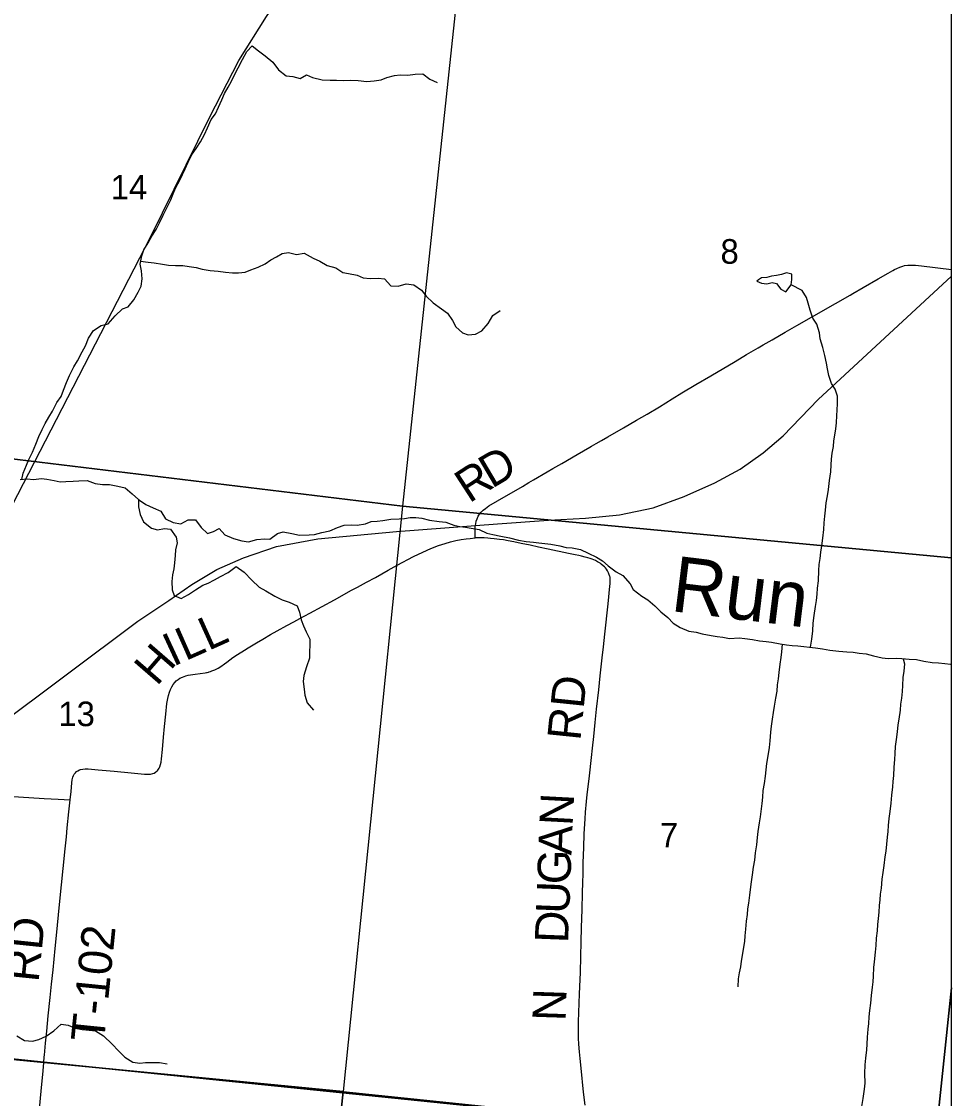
# Model space of a CAD drawing. Extents: x 0 to 1067, y 0 to 440.
# Drawn here: x 803.255 to 804.84, y 353.302 to 355.137 of the extents above; entities that cross this region are included whole.
import ezdxf

# ---------------------------------------------------------------- set-up
doc = ezdxf.new("R2010")
doc.units = 0
for name, color, linetype in [('GM_X_Minor_Lake', 7, 'Continuous'), ('GM_X_Minor_River', 7, 'Continuous'), ('GM_X_Minor_River_Text', 7, 'Continuous'), ('GM_X_Rail_Line', 7, 'Continuous'), ('GM_X_Section', 7, 'Continuous'), ('GM_X_Section_Text', 7, 'Continuous'), ('GM_X_Township_Road', 7, 'Continuous'), ('GM_X_Township_Road_Text', 7, 'Continuous'), ('GM_X_US_Shield', 7, 'Continuous')]:
    doc.layers.add(name, color=color, linetype=linetype)

msp = doc.modelspace()

# ---------------------------------------------------------------- linework, layer by layer
at = {"layer": 'GM_X_Minor_Lake'}
for points in [[(804.5669, 354.6882), (804.5678, 354.6973), (804.5679, 354.7061), (804.5589, 354.7085), (804.5505, 354.7059), (804.5417, 354.7038), (804.5333, 354.7028), (804.5253, 354.7006), (804.5162, 354.7), (804.5113, 354.6964)], [(804.5113, 354.6964), (804.5085, 354.6944), (804.5161, 354.6908), (804.5256, 354.6896), (804.5343, 354.6921), (804.5419, 354.6905), (804.5493, 354.6809), (804.5576, 354.6762), (804.5669, 354.6882)]]:
    msp.add_lwpolyline(points, dxfattribs=at)
at = {"layer": 'GM_X_Minor_River'}
for points in [[(803.2553, 354.3567), (803.2575, 354.3674), (803.2637, 354.3806), (803.2673, 354.3908), (803.2739, 354.4029), (803.2794, 354.4169), (803.2845, 354.4297), (803.2904, 354.4414), (803.2951, 354.4516), (803.3017, 354.4626), (803.3079, 354.4727), (803.3154, 354.4874), (803.3223, 354.4976), (803.3267, 354.5086), (803.3314, 354.5218), (803.3365, 354.5339), (803.3443, 354.5486), (803.3502, 354.5588), (803.3584, 354.5742), (803.3638, 354.5844), (803.3693, 354.5972), (803.3775, 354.6104), (803.3905, 354.619), (803.4027, 354.6219), (803.4147, 354.6354), (803.427, 354.6474), (803.4365, 354.6506), (803.4466, 354.6627), (803.454, 354.6759), (803.4587, 354.6857), (803.4604, 354.6986), (803.4594, 354.7119), (803.4569, 354.7233), (803.4598, 354.7377), (803.4637, 354.7475), (803.4711, 354.7596), (803.477, 354.7709), (803.4843, 354.7822), (803.4902, 354.7939), (803.4965, 354.8067), (803.5023, 354.8184), (803.5094, 354.8327), (803.5137, 354.8429), (803.5176, 354.8527), (803.5246, 354.8663), (803.5293, 354.8761), (803.534, 354.8859), (803.5391, 354.8969), (803.5461, 354.9105), (803.5524, 354.9206), (803.5601, 354.9319), (803.5667, 354.944), (803.5722, 354.9557), (803.5781, 354.9697), (803.5855, 354.9794), (803.5906, 354.9908), (803.5964, 355.0032), (803.6012, 355.0142), (803.6074, 355.0247), (803.6128, 355.0353), (803.6183, 355.047), (803.6242, 355.0579), (803.6316, 355.0719), (803.639, 355.0854), (803.6479, 355.0956), (803.6591, 355.0867), (803.6704, 355.0782), (803.6832, 355.0674), (803.6929, 355.0547), (803.706, 355.0443), (803.7177, 355.0433), (803.7298, 355.0394), (803.7409, 355.0461), (803.7511, 355.0414), (803.7674, 355.0373), (803.7811, 355.0368), (803.7921, 355.037), (803.8046, 355.0364), (803.8156, 355.0367), (803.8289, 355.0361), (803.8437, 355.0348), (803.8562, 355.0357), (803.868, 355.0375), (803.8776, 355.0415), (803.8909, 355.0447), (803.9004, 355.0461), (803.9137, 355.0456), (803.9262, 355.0473), (803.9392, 355.0475), (803.9512, 355.0386), (803.9632, 355.0327)], [(803.458, 354.7285), (803.4706, 354.7265), (803.4809, 354.7256), (803.4953, 354.7232), (803.5055, 354.7219), (803.5173, 354.7213), (803.5298, 354.7212), (803.5408, 354.7195), (803.5525, 354.7174), (803.5627, 354.715), (803.5764, 354.7125), (803.59, 354.7116), (803.6025, 354.7099), (803.6143, 354.7086), (803.6249, 354.7088), (803.6363, 354.7098), (803.6458, 354.7135), (803.6581, 354.7183), (803.6703, 354.7238), (803.6799, 354.7305), (803.6898, 354.7357), (803.6994, 354.7413), (803.7101, 354.7434), (803.7237, 354.7398), (803.737, 354.7419), (803.7521, 354.7333), (803.7634, 354.7282), (803.7758, 354.7208), (803.7906, 354.7172), (803.8026, 354.7091), (803.8124, 354.7074), (803.8272, 354.7046), (803.8374, 354.6999), (803.8495, 354.6989), (803.8628, 354.6995), (803.8734, 354.6986), (803.8843, 354.6867), (803.8972, 354.6861), (803.9105, 354.6901), (803.9238, 354.6884), (803.9369, 354.6791), (803.9448, 354.6691), (803.9564, 354.6572), (803.9707, 354.6471), (803.9808, 354.6398), (803.9897, 354.6271), (803.9953, 354.6164), (804.0065, 354.6064), (804.0163, 354.6028), (804.0289, 354.6038), (804.0396, 354.6097), (804.0504, 354.6221), (804.0582, 354.636), (804.0708, 354.6442)], [(804.5997, 354.0708), (804.602, 354.0846), (804.6037, 354.0986), (804.6046, 354.1119), (804.6063, 354.1248), (804.6081, 354.1403), (804.6101, 354.1502), (804.6114, 354.1612), (804.6119, 354.1714), (804.6133, 354.1839), (804.6143, 354.2014), (804.6148, 354.2117), (804.6161, 354.2219), (804.6177, 354.2325), (804.619, 354.2435), (804.6207, 354.2564), (804.6225, 354.2712), (804.6234, 354.2829), (804.6243, 354.2939), (804.6252, 354.3042), (804.6265, 354.3167), (804.6286, 354.3288), (804.6307, 354.3394), (804.6324, 354.3546), (804.6345, 354.3694), (804.635, 354.3812), (804.6356, 354.391), (804.6369, 354.4013), (804.6389, 354.4126), (804.6398, 354.4221), (804.6411, 354.432), (804.6428, 354.4429), (804.6441, 354.4532), (804.645, 354.4653), (804.6451, 354.4748), (804.6457, 354.4858), (804.6458, 354.4984), (804.6418, 354.5106), (804.6355, 354.5202), (804.6308, 354.5339), (804.6287, 354.5449), (804.6273, 354.5544), (804.624, 354.5678), (804.6208, 354.5815), (804.6165, 354.5964), (804.6151, 354.6063), (804.6104, 354.6212), (804.6037, 354.6311), (804.5993, 354.6449), (804.5961, 354.6571), (804.5928, 354.6666), (804.5858, 354.6785), (804.5669, 354.6882)], [(803.2524, 354.3565), (803.2645, 354.3575), (803.2751, 354.3562), (803.2888, 354.3579), (803.2983, 354.357), (803.3108, 354.3546), (803.321, 354.3525), (803.3305, 354.3528)], [(803.3305, 354.3528), (803.3427, 354.3534), (803.3529, 354.354), (803.3666, 354.3549), (803.3802, 354.3498), (803.3931, 354.3477), (803.4049, 354.3479), (803.4193, 354.3451), (803.4317, 354.3423), (803.4434, 354.3322), (803.4546, 354.3226), (803.467, 354.3137), (803.4791, 354.3082), (803.4923, 354.3027), (803.5001, 354.2893), (803.5133, 354.2834), (803.5265, 354.281), (803.5392, 354.2876), (803.5513, 354.2878), (803.561, 354.2748), (803.5719, 354.2644), (803.5822, 354.2677), (803.5917, 354.2732), (803.6014, 354.2621), (803.6165, 354.2558), (803.6305, 354.2518), (803.6419, 354.2505), (803.656, 354.2545), (803.6689, 354.2551), (803.6784, 354.2546), (803.6915, 354.2647), (803.701, 354.2672), (803.7158, 354.2647), (803.729, 354.2619), (803.745, 354.262), (803.7545, 354.263), (803.7667, 354.2663), (803.7804, 354.2691), (803.7934, 354.2747), (803.8052, 354.2787), (803.8166, 354.2793), (803.8272, 354.2784), (803.8413, 354.2808), (803.8508, 354.2849), (803.8611, 354.2855), (803.8706, 354.2865), (803.8843, 354.2886), (803.8984, 354.2896), (803.9079, 354.2902), (803.9174, 354.2916), (803.9269, 354.2918), (803.9371, 354.2905), (803.9503, 354.2873), (803.967, 354.2848), (803.978, 354.2839), (803.992, 354.2784), (804.0022, 354.2764), (804.012, 354.2751), (804.0215, 354.2738), (804.0351, 354.271), (804.0483, 354.2651), (804.0582, 354.2627), (804.0722, 354.2598), (804.087, 354.257), (804.1021, 354.2529), (804.115, 354.2509), (804.1275, 354.2496), (804.137, 354.2487), (804.1468, 354.2474), (804.1574, 354.2461), (804.1726, 354.2432), (804.1835, 354.2408), (804.1938, 354.2399), (804.2078, 354.2371), (804.2206, 354.2312), (804.2353, 354.2241), (804.2451, 354.2179), (804.2552, 354.2091), (804.2688, 354.1994), (804.2797, 354.1928), (804.2924, 354.1789), (804.2976, 354.1693), (804.3126, 354.1577), (804.3224, 354.1512), (804.3344, 354.1411), (804.3448, 354.1311), (804.3569, 354.1214), (804.3658, 354.1118), (804.3779, 354.1044), (804.3926, 354.0981), (804.4051, 354.0964), (804.4149, 354.0937), (804.4305, 354.0908), (804.4407, 354.0891), (804.4505, 354.0878), (804.4615, 354.0858), (804.4782, 354.0867), (804.4881, 354.0858), (804.501, 354.0837), (804.5127, 354.0817), (804.5241, 354.0804)], [(803.4543, 354.3229), (803.4544, 354.31), (803.4573, 354.2967), (803.4628, 354.2845), (803.4767, 354.2737), (803.4869, 354.2709), (803.4987, 354.273), (803.509, 354.2721), (803.5183, 354.2583), (803.52, 354.2484), (803.5176, 354.2366), (803.517, 354.2268), (803.5157, 354.2142), (803.5144, 354.2044), (803.5124, 354.1938), (803.5111, 354.1828), (803.5117, 354.1687), (803.5153, 354.1588), (803.527, 354.1537), (803.5393, 354.1604), (803.5515, 354.1686), (803.5638, 354.1764), (803.5733, 354.18), (803.584, 354.1856), (803.594, 354.1911), (803.6074, 354.1982), (803.6208, 354.2083), (803.6347, 354.1986), (803.6474, 354.1847), (803.6602, 354.1732), (803.6715, 354.1665), (803.6869, 354.1576), (803.699, 354.1517), (803.7111, 354.1474), (803.7246, 354.1411), (803.729, 354.1304), (803.7315, 354.1171), (803.7355, 354.1072), (803.74, 354.0972), (803.7462, 354.0842), (803.7465, 354.0743), (803.7459, 354.0626), (803.7461, 354.0519), (803.7406, 354.0372), (803.7362, 354.0228), (803.7349, 354.0122), (803.7367, 353.9993), (803.738, 353.989), (803.7416, 353.976), (803.7525, 353.9637)], [(804.5518, 354.0761), (804.5504, 354.0629), (804.5491, 354.053), (804.5478, 354.0417), (804.5461, 354.0276), (804.5448, 354.0166), (804.5431, 354.0064), (804.5422, 353.9958), (804.5402, 353.9837), (804.5377, 353.97), (804.536, 353.9594), (804.5347, 353.9484), (804.533, 353.9363), (804.5317, 353.9257), (804.5304, 353.9112), (804.5291, 353.8999), (804.5278, 353.8892), (804.5249, 353.8726), (804.5236, 353.862), (804.5227, 353.851), (804.5206, 353.8384), (804.5186, 353.8267), (804.518, 353.8153), (804.5167, 353.8047), (804.5155, 353.7952), (804.5138, 353.7819), (804.5121, 353.7713), (804.5103, 353.7565), (804.5091, 353.7463), (804.5078, 353.7342), (804.5057, 353.7205), (804.5043, 353.708), (804.5023, 353.6959), (804.5002, 353.683), (804.4989, 353.6709), (804.4968, 353.658), (804.4959, 353.6485), (804.4942, 353.6348), (804.4925, 353.625), (804.4916, 353.6155), (804.4899, 353.6037), (804.489, 353.5901), (804.4881, 353.5787), (804.4876, 353.5692), (804.4859, 353.5597), (804.4838, 353.5487), (804.4818, 353.5359), (804.4805, 353.526), (804.4784, 353.5161), (804.4768, 353.5055), (804.4762, 353.4919)], [(804.5241, 354.0804), (804.5336, 354.0791), (804.5483, 354.0766), (804.5589, 354.0749), (804.5688, 354.0737), (804.5783, 354.0728), (804.5885, 354.0719), (804.5984, 354.071), (804.6086, 354.0697), (804.6203, 354.068), (804.6328, 354.0659), (804.648, 354.0642), (804.662, 354.0629), (804.6723, 354.062), (804.6829, 354.0607), (804.6946, 354.0594), (804.7071, 354.0561), (804.7219, 354.0529), (804.7321, 354.0516), (804.7458, 354.0522), (804.7556, 354.0513), (804.7681, 354.0503), (804.7803, 354.0498), (804.7928, 354.047), (804.8075, 354.0448), (804.8178, 354.0439), (804.8288, 354.0427), (804.8383, 354.0421), (804.8401, 354.0419)], [(804.7577, 354.0511), (804.7601, 354.0425), (804.7587, 354.03), (804.7574, 354.019), (804.7569, 354.0053), (804.756, 353.9954), (804.7551, 353.9841), (804.7534, 353.9734), (804.7525, 353.9636), (804.7504, 353.948), (804.7487, 353.9386), (804.7474, 353.9264), (804.7461, 353.9135), (804.7444, 353.9018), (804.7435, 353.8896), (804.7429, 353.8794), (804.742, 353.8665), (804.7414, 353.8524), (804.7401, 353.8422), (804.7396, 353.8327), (804.7379, 353.8187), (804.7366, 353.805), (804.7352, 353.791), (804.7335, 353.7789), (804.7322, 353.7671), (804.7317, 353.7565), (804.7308, 353.747), (804.7295, 353.7349), (804.7282, 353.7235), (804.7265, 353.7133), (804.7248, 353.6988), (804.7231, 353.6867), (804.7214, 353.6753), (804.7201, 353.6602), (804.7188, 353.6499), (804.7179, 353.6404), (804.717, 353.6306), (804.7161, 353.6192), (804.7151, 353.6086), (804.7142, 353.5983), (804.7133, 353.5877), (804.712, 353.5752), (804.7111, 353.5623), (804.7098, 353.5513), (804.7084, 353.5346), (804.7075, 353.5251), (804.7069, 353.5103), (804.706, 353.5008), (804.7047, 353.4913), (804.7034, 353.4773), (804.7021, 353.4644), (804.7004, 353.4515), (804.6991, 353.4409), (804.6985, 353.4295), (804.6973, 353.42), (804.6963, 353.4064), (804.6961, 353.3942), (804.6952, 353.3847), (804.6935, 353.3703), (804.6922, 353.3593), (804.6918, 353.3442)], [(803.2472, 353.4084), (803.26, 353.4006), (803.2737, 353.3997), (803.2843, 353.4022), (803.2969, 353.4081), (803.31, 353.4174), (803.3223, 353.4283), (803.3344, 353.427), (803.3465, 353.4215), (803.3586, 353.4194), (803.3704, 353.4185), (803.381, 353.4172), (803.3949, 353.4087), (803.4095, 353.3944), (803.42, 353.3833), (803.4308, 353.3721), (803.4444, 353.3636), (803.4565, 353.3622), (803.466, 353.3629), (803.4782, 353.3631), (803.4899, 353.3633), (803.5032, 353.3609)], [(804.6918, 353.3442), (804.6926, 353.3278), (804.6914, 353.3179), (804.689, 353.302), (804.687, 353.2884)]]:
    msp.add_lwpolyline(points, dxfattribs=at)
at = {"layer": 'GM_X_Rail_Line'}
for points in [[(802.6661, 353.2687), (802.697, 353.3096), (802.7308, 353.3638), (802.8122, 353.4875), (802.8565, 353.5668), (802.8978, 353.6472), (802.9601, 353.7689), (803.2011, 354.2396), (803.4754, 354.7705), (803.5751, 354.9733), (803.6255, 355.0706), (803.6726, 355.1455), (803.7251, 355.2226), (803.7723, 355.2875), (803.8221, 355.3565), (804.0447, 355.6231), (804.2946, 355.9212), (804.7631, 356.4702), (804.8401, 356.5624)], [(803.2081, 353.9324), (803.4534, 354.1151), (803.506, 354.1504), (803.5455, 354.1774), (803.5878, 354.2031), (803.6336, 354.223), (803.6895, 354.2422), (803.7601, 354.2554), (803.8942, 354.2679), (804.0665, 354.2809), (804.1535, 354.2872), (804.2165, 354.2904), (804.2744, 354.2964), (804.3315, 354.3081), (804.3846, 354.3275), (804.4367, 354.3506), (804.4801, 354.3739), (804.5191, 354.4018), (804.5535, 354.4306), (804.613, 354.4926), (804.8401, 354.703)]]:
    msp.add_lwpolyline(points, dxfattribs=at)
at = {"layer": 'GM_X_Section'}
for points in [[(804.0106, 355.307), (803.9043, 354.3108), (802.8724, 354.4357), (802.9708, 355.4138)], [(803.9043, 354.3108), (803.8031, 353.3139), (802.7829, 353.4125), (802.8724, 354.4357)], [(803.8031, 353.3139), (803.6983, 352.312), (802.6931, 352.4236), (802.7829, 353.4125)], [(804.8106, 353.2091), (804.7094, 352.2121), (804.2114, 352.247), (803.6983, 352.312), (803.8031, 353.3139)]]:
    msp.add_lwpolyline(points, close=True, dxfattribs=at)
at = {"layer": 'GM_X_Township_Road'}
for points in [[(804.8401, 353.205), (804.8401, 357.6021)], [(804.0283, 354.2568), (804.0284, 354.2717), (804.0285, 354.2761), (804.0292, 354.2811), (804.0301, 354.2855), (804.0314, 354.2897), (804.0332, 354.2938), (804.0357, 354.2975), (804.0385, 354.3009), (804.0417, 354.304), (804.0456, 354.3072), (804.0518, 354.3115), (804.0662, 354.3202), (804.1087, 354.3448), (804.1199, 354.3514), (804.1279, 354.3561), (804.151, 354.3696), (804.1608, 354.375), (804.1758, 354.3837), (804.2021, 354.399), (804.2235, 354.4116), (804.2267, 354.4135), (804.2343, 354.4177), (804.2435, 354.4228), (804.2543, 354.4289), (804.2812, 354.4444), (804.3032, 354.4573), (804.3213, 354.468), (804.3422, 354.4804), (804.3638, 354.4938), (804.3807, 354.5043), (804.4042, 354.5183), (804.43, 354.5332), (804.4712, 354.5576), (804.4909, 354.5695), (804.5107, 354.581), (804.5193, 354.586), (804.5344, 354.5946), (804.5565, 354.6072), (804.5764, 354.6187), (804.6017, 354.6333), (804.6422, 354.6564), (804.6676, 354.6708), (804.6719, 354.6733), (804.6896, 354.6835), (804.7149, 354.6982), (804.7321, 354.7081), (804.7403, 354.7126), (804.7431, 354.714), (804.7468, 354.7162), (804.752, 354.7184), (804.7575, 354.7202), (804.7599, 354.7208), (804.7656, 354.7216), (804.7712, 354.7219), (804.7787, 354.7215), (804.7893, 354.7203), (804.8401, 354.7142)], [(803.338, 353.8109), (803.3393, 353.8249), (803.3405, 353.8398), (803.3412, 353.8448), (803.3423, 353.8492), (803.3436, 353.8521), (803.3449, 353.8544), (803.3469, 353.8569), (803.3488, 353.8587), (803.3509, 353.8602), (803.3538, 353.8617), (803.3556, 353.8624), (803.3594, 353.8632), (803.3632, 353.8635), (803.3683, 353.8634), (803.3857, 353.862), (803.4129, 353.8597), (803.442, 353.8568), (803.4648, 353.8547), (803.4698, 353.8545), (803.4746, 353.8547), (803.4787, 353.8555), (803.4809, 353.8564), (803.4835, 353.8577), (803.4863, 353.86), (803.4875, 353.8612), (803.4898, 353.8646), (803.4907, 353.8668), (803.4921, 353.8708), (803.4929, 353.875), (803.4937, 353.8805), (803.4953, 353.8966), (803.4971, 353.9176), (803.4987, 353.9356), (803.5007, 353.9566), (803.5029, 353.9751), (803.5042, 353.9832), (803.5054, 353.9887), (803.507, 353.9941), (803.5088, 353.9989), (803.511, 354.0034), (803.5133, 354.0072), (803.516, 354.0107), (803.5187, 354.0134), (803.5217, 354.0158), (803.5249, 354.0178), (803.5295, 354.0199), (803.5348, 354.022), (803.5391, 354.0231), (803.5508, 354.0249), (803.5679, 354.0273), (803.5703, 354.0277), (803.5714, 354.0278), (803.5736, 354.0284), (803.5748, 354.0286), (803.5769, 354.0294), (803.5791, 354.0302), (803.5847, 354.0324), (803.5901, 354.0352), (803.5948, 354.0381), (803.6008, 354.0424), (803.6048, 354.0453), (803.6153, 354.053), (803.6231, 354.0582), (803.6352, 354.0659), (803.6415, 354.0698), (803.6469, 354.073), (803.6554, 354.0782), (803.666, 354.0845), (803.6795, 354.0923), (803.6909, 354.0985), (803.7072, 354.1075), (803.7191, 354.114), (803.7295, 354.1196), (803.7464, 354.1288), (803.7677, 354.1403), (803.7884, 354.1516), (803.8177, 354.1678), (803.8276, 354.1731), (803.8429, 354.1814), (803.8581, 354.1897), (803.8797, 354.202), (803.8955, 354.2106), (803.923, 354.2252), (803.9314, 354.2293), (803.9524, 354.2387), (803.9658, 354.2439), (803.977, 354.2477), (803.986, 354.2503), (803.9951, 354.2525), (804.0043, 354.2542), (804.0129, 354.2554), (804.0197, 354.2561), (804.0283, 354.2568)], [(804.2157, 353.2907), (804.2131, 353.3129), (804.2087, 353.3537), (804.2071, 353.3698), (804.206, 353.3816), (804.205, 353.3946), (804.2044, 353.4045), (804.2042, 353.4151), (804.2045, 353.4325), (804.2062, 353.4804), (804.207, 353.5046), (804.2075, 353.5164), (804.2083, 353.5437), (804.2087, 353.5685), (804.2093, 353.5934), (804.2106, 353.6238), (804.2113, 353.6524), (804.2118, 353.6697), (804.2122, 353.6846), (804.2126, 353.7033), (804.213, 353.7163), (804.2134, 353.7294), (804.2143, 353.7529), (804.2156, 353.7784), (804.2164, 353.7896), (804.2182, 353.8081), (804.2194, 353.8199), (804.2213, 353.8372), (804.2229, 353.8514), (804.2263, 353.8828), (804.2281, 353.8989), (804.2303, 353.9186), (804.233, 353.9427), (804.2353, 353.965), (804.239, 353.9983), (804.2415, 354.0218), (804.2447, 354.0527), (804.2468, 354.0712), (804.2492, 354.0928), (804.2549, 354.1447), (804.258, 354.1749), (804.2583, 354.1786), (804.2585, 354.181), (804.2586, 354.1829), (804.2586, 354.1848), (804.2586, 354.1858), (804.2586, 354.1868), (804.2585, 354.1879), (804.2583, 354.189), (804.2581, 354.1899), (804.2578, 354.1911), (804.2574, 354.1927), (804.2568, 354.1943), (804.2555, 354.1977), (804.2539, 354.2009), (804.2519, 354.2039), (804.2503, 354.2059), (804.2486, 354.2075), (804.2466, 354.2094), (804.2429, 354.2124), (804.2411, 354.2137), (804.237, 354.2164), (804.2352, 354.2174), (804.2332, 354.2185), (804.2307, 354.2196), (804.2275, 354.2208), (804.2242, 354.2219), (804.22, 354.2231), (804.2155, 354.2242), (804.2097, 354.2256), (804.2048, 354.2267), (804.1986, 354.228), (804.1873, 354.2304), (804.1528, 354.2378), (804.1361, 354.2414), (804.1217, 354.2445), (804.1064, 354.2477), (804.0943, 354.2502), (804.0843, 354.252), (804.0763, 354.2534), (804.0696, 354.2545), (804.0606, 354.2556), (804.0544, 354.2562), (804.0499, 354.2565), (804.0437, 354.2569), (804.038, 354.257), (804.0336, 354.2569), (804.0283, 354.2568)], [(803.2324, 353.8167), (803.2938, 353.8129), (803.3174, 353.8116), (803.338, 353.8109)], [(803.294, 353.3757), (803.2959, 353.3961), (803.298, 353.4165), (803.3006, 353.4424), (803.3036, 353.474), (803.306, 353.4968), (803.3086, 353.5209), (803.3122, 353.5574), (803.3144, 353.5796), (803.3199, 353.6321), (803.3295, 353.7273), (803.3315, 353.7477), (803.333, 353.7631), (803.3357, 353.7903), (803.338, 353.8109)], [(802.7875, 353.4167), (803.2927, 353.3636), (804.2178, 353.2689)], [(804.2178, 353.2689), (803.2927, 353.3636), (802.7875, 353.4167)], [(803.293, 353.3631), (803.2937, 353.3726), (803.294, 353.3757)], [(803.2844, 353.2671), (803.2858, 353.2842), (803.2886, 353.3145), (803.2918, 353.3491), (803.293, 353.3631)]]:
    msp.add_lwpolyline(points, dxfattribs=at)
at = {"layer": 'GM_X_US_Shield'}
for points in [[(804.8401, 354.2229), (804.8401, 355.211), (804.0106, 355.307), (803.9043, 354.3108)], [(804.8401, 353.4905), (804.8401, 354.2229), (803.9043, 354.3108), (803.8031, 353.3139), (804.8106, 353.2091)], [(804.8401, 353.2061), (804.8401, 353.4905), (804.8106, 353.2091)]]:
    msp.add_lwpolyline(points, close=True, dxfattribs=at)

# ---------------------------------------------------------------- texts
at = {"layer": 'GM_X_Minor_River_Text'}
msp.add_text('Run', height=0.0947, rotation=352.9996, dxfattribs=at).set_placement((804.3596, 354.1326))
at = {"layer": 'GM_X_Section_Text'}
for s, height, p in [('14', 0.04186, (803.4069, 354.8336)), ('8', 0.0419, (804.4464, 354.7241)), ('13', 0.04186, (803.3177, 353.9362)), ('7', 0.0419, (804.3431, 353.7296))]:
    msp.add_text(s, height=height, rotation=0, dxfattribs=at).set_placement(p)
at = {"layer": 'GM_X_Township_Road_Text'}
for s, height, rotation, p in [('D', 0.0568, 30.5546, (804.0566, 354.3403)), ('R', 0.0568, 32.9756, (804.018, 354.3152)), ('L', 0.0568, 24.2747, (803.5734, 354.0642)), ('L', 0.0568, 23.9442, (803.5342, 354.0468)), ('I', 0.0568, 24.8613, (803.5133, 354.0371)), ('H', 0.0568, 49.1095, (803.4856, 354.0031)), ('RD', 0.05682, 84.1435, (804.2075, 353.9104)), ('N', 0.0568, 86.9933, (804.1942, 353.7656)), ('A', 0.0568, 87.8063, (804.1923, 353.7158)), ('G', 0.0568, 87.8065, (804.1904, 353.6659)), ('U', 0.0568, 87.8101, (804.1885, 353.6159)), ('RD', 0.05682, 84.0953, (803.2838, 353.4989)), ('D', 0.0568, 87.8065, (804.1865, 353.5659)), ('T-102', 0.05682, 84.1839, (803.3954, 353.3965)), ('N', 0.0568, 88.1232, (804.1824, 353.4331))]:
    msp.add_text(s, height=height, rotation=rotation, dxfattribs=at).set_placement(p)

doc.saveas('drawing.dxf')
